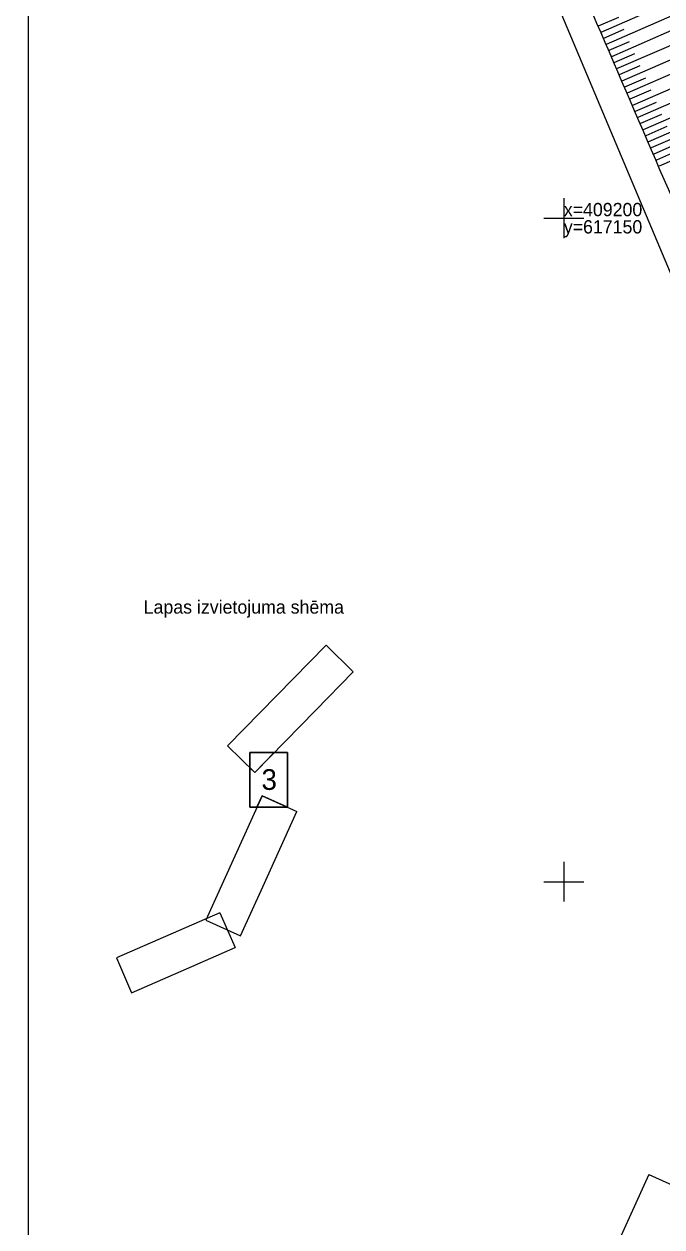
# Model space of a CAD drawing. Extents: x 616607 to 617499, y 408385 to 409695.
# Drawn here: x 617109.3 to 617157.4, y 409124 to 409214.6 of the extents above; entities that cross this region are included whole.
import ezdxf

# ---------------------------------------------------------------- set-up
doc = ezdxf.new("R2010")
doc.units = 0
for name, color, linetype in [('GEOD_ELEM_####_####_#', 7, 'Continuous'), ('GEOD_KORD_####_TKST_#', 7, 'Continuous'), ('RAMI_PLAN_####_TKST_#', 7, 'Continuous'), ('RAMI_UZMR_####_####_#', 7, 'Continuous'), ('RELJ_NOGA_####_####_#', 7, 'Continuous')]:
    doc.layers.add(name, color=color, linetype=linetype)

# ---------------------------------------------------------------- blocks, each defined once
blk = doc.blocks.new('KRUSTS')
at = {"layer": 'GEOD_ELEM_####_####_#'}
for p, q in [((0, 1.5), (0, 0)), ((-1.5, 0), (0, 0)), ((0, 0), (0, -1.5)), ((0, 0), (1.5, 0))]:
    blk.add_line(p, q, dxfattribs=at)

msp = doc.modelspace()

# ---------------------------------------------------------------- linework, layer by layer
at = {"layer": 'RAMI_PLAN_####_TKST_#'}
for p, q in [((617124.666, 409160.229), (617132.085, 409167.823)), ((617132.085, 409167.823), (617134.137, 409165.819)), ((617134.137, 409165.819), (617131.291, 409162.906)), ((617131.291, 409162.906), (617126.718, 409158.225)), ((617124.666, 409160.229), (617126.718, 409158.225)), ((617127.277, 409156.478), (617123.019, 409147.096)), ((617127.277, 409156.478), (617129.888, 409155.293)), ((617127.313, 409149.619), (617129.888, 409155.293)), ((617125.631, 409145.911), (617127.313, 409149.619)), ((617124.08, 409147.659), (617116.286, 409144.257)), ((617123.019, 409147.096), (617125.631, 409145.911)), ((617124.08, 409147.659), (617125.228, 409145.03)), ((617116.286, 409144.257), (617117.434, 409141.628)), ((617121.166, 409143.257), (617125.228, 409145.03)), ((617117.434, 409141.628), (617121.166, 409143.257)), ((617156.405, 409127.944), (616943.506, 408658.834)), ((617156.405, 409127.944), (617287, 409068.676))]:
    msp.add_line(p, q, dxfattribs=at)
for points in [[(617109.674, 409084.461), (617109.674, 409290.339), (617251.246, 409290.339), (617251.246, 409084.461), (617109.674, 409084.461)], [(617126.342, 409155.609), (617126.342, 409159.726), (617129.173, 409159.726), (617129.173, 409155.609), (617126.342, 409155.609)]]:
    msp.add_lwpolyline(points, dxfattribs=at)
for points in [[(617126.718, 409158.225), (617126.342, 409158.592), (617126.342, 409155.609), (617126.882, 409155.609), (617127.277, 409156.478), (617129.173, 409155.618), (617129.173, 409159.726), (617128.185, 409159.726)], [(617126.342, 409159.726), (617126.342, 409158.592), (617126.718, 409158.225), (617128.185, 409159.726)], [(617129.173, 409155.609), (617129.173, 409155.618), (617127.277, 409156.478), (617126.882, 409155.609)]]:
    msp.add_lwpolyline(points, close=True, dxfattribs=at)
at = {"layer": 'RAMI_UZMR_####_####_#'}
msp.add_lwpolyline([(617101.571, 408748.246), (617213.472, 409074.039), (617215.883, 409140.56), (617165.121, 409241.478), (617252.137, 409353.424), (617269.572, 409425.099), (617332.631, 409510.312), (617439.945, 409622.037), (617425.373, 409635.959), (617242.079, 409440.82), (617216.614, 409355.716), (617136.613, 409246.751), (617191.828, 409115.62), (617145.545, 408952.8)], dxfattribs=at)
at = {"layer": 'RELJ_NOGA_####_####_#'}
for p, q in [((617152.812, 409214.028), (617157.93, 409216.242)), ((617152.614, 409214.487), (617154.145, 409215.149)), ((617153.209, 409213.11), (617158.352, 409215.338)), ((617152.614, 409214.487), (617152.613, 409214.487)), ((617153.011, 409213.569), (617154.55, 409214.235)), ((617153.607, 409212.193), (617158.773, 409214.434)), ((617152.812, 409214.028), (617152.811, 409214.028)), ((617153.011, 409213.569), (617153.01, 409213.569)), ((617153.408, 409212.652), (617154.955, 409213.321)), ((617154.005, 409211.275), (617159.196, 409213.527)), ((617153.209, 409213.11), (617153.209, 409213.11)), ((617153.408, 409212.652), (617153.408, 409212.651)), ((617153.806, 409211.734), (617155.36, 409212.408)), ((617154.403, 409210.358), (617159.618, 409212.623)), ((617153.607, 409212.193), (617153.606, 409212.192)), ((617153.806, 409211.734), (617153.806, 409211.734)), ((617154.204, 409210.817), (617155.765, 409211.495)), ((617154.802, 409209.441), (617160.039, 409211.72)), ((617154.005, 409211.275), (617154.004, 409211.275)), ((617154.204, 409210.817), (617154.204, 409210.816)), ((617154.602, 409209.899), (617156.17, 409210.581)), ((617155.201, 409208.524), (617160.462, 409210.813)), ((617154.403, 409210.358), (617154.402, 409210.358)), ((617154.602, 409209.899), (617154.602, 409209.899)), ((617155.001, 409208.982), (617156.576, 409209.668)), ((617155.6, 409207.607), (617160.883, 409209.91)), ((617154.802, 409209.441), (617154.801, 409209.44)), ((617155.001, 409208.982), (617155.001, 409208.982)), ((617155.4, 409208.065), (617156.982, 409208.754)), ((617155.999, 409206.69), (617161.306, 409209.004)), ((617155.201, 409208.524), (617155.2, 409208.523)), ((617155.4, 409208.065), (617155.4, 409208.065)), ((617155.8, 409207.149), (617157.388, 409207.841)), ((617156.399, 409205.774), (617161.726, 409208.101)), ((617155.6, 409207.607), (617155.599, 409207.607)), ((617155.8, 409207.149), (617155.799, 409207.149)), ((617156.199, 409206.232), (617157.794, 409206.929)), ((617156.8, 409204.857), (617162.145, 409207.193)), ((617155.999, 409206.69), (617155.999, 409206.69)), ((617156.199, 409206.232), (617156.199, 409206.232)), ((617156.6, 409205.316), (617158.201, 409206.015)), ((617157.201, 409203.941), (617162.553, 409206.283)), ((617156.399, 409205.774), (617156.399, 409205.773)), ((617156.6, 409205.316), (617156.599, 409205.316)), ((617157, 409204.399), (617158.604, 409205.101)), ((617156.8, 409204.857), (617156.799, 409204.857)), ((617157, 409204.399), (617157, 409204.399)), ((617157.201, 409203.941), (617157.2, 409203.941))]:
    msp.add_line(p, q, dxfattribs=at)
for points in [[(617336.806, 409523.735), (617334.087, 409521.174), (617331.368, 409518.613), (617328.65, 409516.053), (617321.193, 409509.03), (617314.57, 409501.094), (617308.568, 409492.793), (617305.546, 409488.614), (617302.537, 409484.426), (617299.516, 409480.247), (617296.49, 409476.063), (617293.469, 409471.875), (617290.436, 409467.695), (617287.772, 409464.025), (617284.965, 409460.461), (617282.252, 409456.826), (617279.55, 409453.205), (617276.887, 409449.558), (617274.256, 409445.882), (617271.624, 409442.206), (617269.17, 409438.414), (617266.782, 409434.573), (617265.581, 409432.642), (617264.455, 409430.674), (617263.346, 409428.69), (617262.228, 409426.69), (617261.169, 409424.668), (617260.166, 409422.606), (617258.56, 409419.302), (617257.132, 409415.931), (617255.903, 409412.47), (617254.682, 409409.035), (617253.531, 409405.585), (617252.579, 409402.073), (617251.627, 409398.563), (617250.683, 409395.052), (617249.746, 409391.538), (617248.81, 409388.023), (617247.876, 409384.508), (617246.956, 409380.989), (617246.456, 409379.078), (617246.028, 409377.149), (617245.649, 409375.21), (617245.269, 409373.268), (617244.984, 409371.31), (617244.622, 409369.366), (617244.259, 409367.42), (617243.878, 409365.48), (617243.456, 409363.545), (617243.245, 409362.576), (617242.967, 409361.625), (617242.691, 409360.672), (617242.413, 409359.713), (617242.093, 409358.772), (617241.734, 409357.838), (617241.092, 409356.173), (617240.315, 409354.578), (617239.389, 409353.048), (617238.465, 409351.519), (617237.498, 409350.034), (617236.402, 409348.636), (617235.3, 409347.23), (617234.195, 409345.828), (617233.083, 409344.431), (617231.973, 409343.038), (617230.863, 409341.647), (617229.743, 409340.262), (617227.764, 409337.815), (617225.693, 409335.438), (617223.461, 409333.217), (617221.215, 409330.983), (617218.873, 409328.856), (617216.607, 409326.646), (617214.346, 409324.442), (617212.093, 409322.231), (617209.875, 409319.98), (617208.771, 409318.86), (617207.791, 409317.635), (617206.772, 409316.432), (617205.753, 409315.229), (617204.825, 409314.017), (617203.96, 409312.646), (617203.768, 409312.342), (617203.633, 409312.004), (617203.62, 409311.655), (617203.607, 409311.284), (617203.603, 409310.913), (617203.599, 409310.542), (617203.595, 409310.167), (617203.603, 409309.793), (617203.596, 409309.419), (617203.588, 409309.066), (617203.48, 409308.714), (617203.309, 409308.4), (617202.615, 409307.13), (617201.9, 409305.914), (617201.16, 409304.689), (617200.419, 409303.462), (617199.689, 409302.232), (617198.921, 409301.021), (617197.385, 409298.6), (617195.744, 409296.251), (617194.012, 409293.966), (617188.331, 409286.47), (617182.548, 409279.072), (617176.617, 409271.78), (617175.091, 409269.904), (617173.565, 409268.03), (617172.006, 409266.181), (617170.46, 409264.348), (617168.875, 409262.548), (617167.326, 409260.717), (617165.749, 409258.854), (617164.19, 409256.978), (617162.652, 409255.082), (617161.86, 409254.106), (617161.109, 409253.1), (617160.341, 409252.105), (617159.552, 409251.081), (617158.796, 409250.055), (617158.061, 409248.97), (617157.091, 409247.54), (617156.549, 409245.874), (617156.301, 409244.175), (617156.178, 409243.327), (617156.153, 409242.478), (617156.175, 409241.631), (617156.198, 409240.798), (617156.24, 409239.966), (617156.347, 409239.134), (617156.709, 409236.311), (617157.141, 409233.481), (617158.294, 409230.866), (617161.329, 409223.986), (617164.552, 409217.339), (617167.894, 409210.677), (617170.758, 409204.966), (617173.578, 409199.236), (617176.506, 409193.56), (617179.423, 409187.907), (617182.384, 409182.277), (617185.301, 409176.624), (617188.243, 409170.922), (617191.171, 409165.213), (617194.071, 409159.489), (617195.541, 409156.585), (617196.952, 409153.652), (617198.382, 409150.727), (617199.832, 409147.761), (617201.227, 409144.774), (617202.61, 409141.772), (617203.681, 409139.449), (617204.533, 409137.047), (617205.282, 409134.589), (617206.022, 409132.164), (617206.554, 409129.71), (617206.943, 409127.212), (617207.329, 409124.726), (617207.611, 409122.242), (617207.809, 409119.738), (617208.005, 409117.248), (617208.126, 409114.753), (617208.097, 409112.263), (617208.074, 409110.266), (617207.983, 409108.256), (617207.635, 409106.282), (617207.283, 409104.281), (617206.913, 409102.294), (617206.558, 409100.3), (617206.203, 409098.306), (617205.85, 409096.331), (617205.506, 409094.315), (617205.165, 409092.324), (617205.06, 409090.322), (617205.116, 409088.325), (617205.171, 409086.355), (617205.316, 409084.384), (617205.484, 409082.414), (617205.653, 409080.435), (617205.914, 409078.469), (617206.09, 409076.495), (617206.126, 409076.085), (617206.005, 409075.66), (617206.103, 409075.26)], [(617191.5, 409068.875), (617191.187, 409071.639), (617190.873, 409074.403), (617190.56, 409077.167), (617188.889, 409091.892), (617197.619, 409106.66), (617195.165, 409121.386), (617194.844, 409123.312), (617194.157, 409125.135), (617193.325, 409126.9), (617187.756, 409138.717), (617181.857, 409150.154), (617176.29, 409161.887), (617165.241, 409185.172), (617154.985, 409208.835), (617144.902, 409232.447), (617143.246, 409236.327), (617146.946, 409242.229), (617143.832, 409245.09), (617142.81, 409246.028), (617141.789, 409246.966), (617140.768, 409247.904)]]:
    msp.add_open_spline(points, degree=3, dxfattribs=at)

# ---------------------------------------------------------------- block references
at = {"layer": 'GEOD_ELEM_####_####_#'}
for p in [(617150, 409200), (617150, 409150)]:
    msp.add_blockref('KRUSTS', p, dxfattribs=at)

# ---------------------------------------------------------------- texts
at = {"layer": 'GEOD_KORD_####_TKST_#'}
for s, p in [('x=409200', (617150, 409200.15)), ('y=617150', (617150, 409198.85))]:
    msp.add_text(s, height=1, dxfattribs=at).set_placement(p)
at = {"layer": 'RAMI_PLAN_####_TKST_#'}
for s, height, p in [('Lapas izvietojuma shēma', 1, (617118.344, 409170.201)), ('3', 1.562, (617127.221, 409156.919))]:
    msp.add_text(s, height=height, dxfattribs=at).set_placement(p)

doc.saveas('drawing.dxf')
